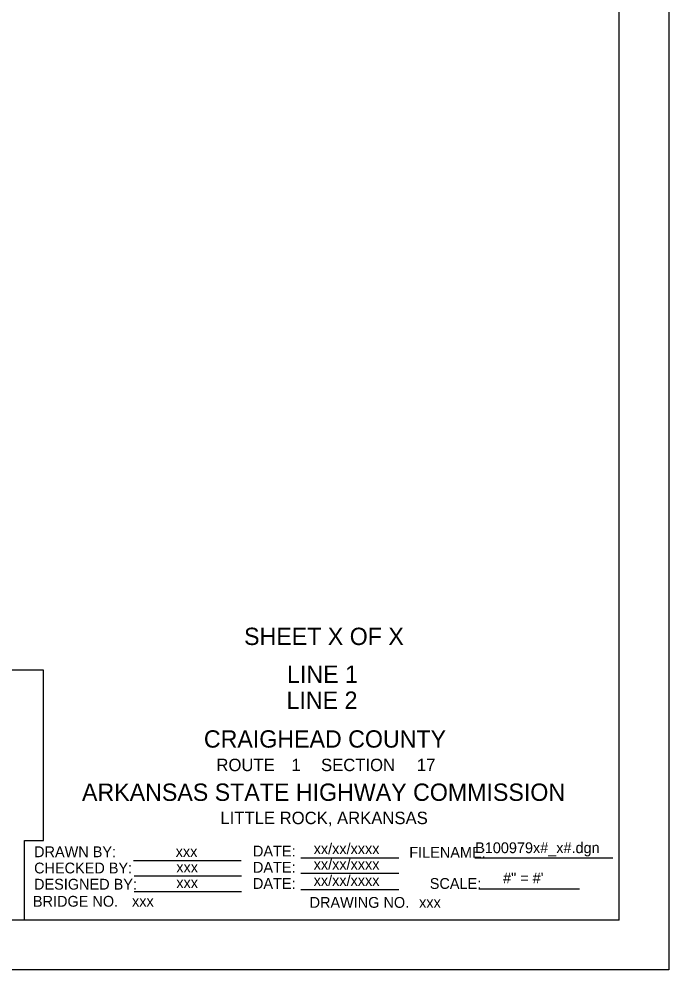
# Model space of a CAD drawing. Extents: x 16 to 1228740, y 11 to 152440.
# Drawn here: x 17.864 to 18.49, y 10.709 to 11.626 of the extents above; entities that cross this region are included whole.
import ezdxf

# ---------------------------------------------------------------- set-up
doc = ezdxf.new("R2010")
doc.units = 0
for name, color, linetype in [('B_Copy In', 7, 'Continuous'), ('B_County and Route', 7, 'Continuous'), ('B_Text', 7, 'Continuous'), ('B_Title Text', 7, 'Continuous'), ('R_Border', 7, 'Continuous'), ('R_No Plot', 7, 'Continuous')]:
    doc.layers.add(name, color=color, linetype=linetype)

msp = doc.modelspace()

# ---------------------------------------------------------------- linework, layer by layer
at = {"layer": 'B_Text'}
for p, q in [((18.13559, 10.81765), (18.23009, 10.81765)), ((18.30318, 10.81765), (18.43623, 10.81765)), ((17.97449, 10.81515), (18.07809, 10.81515)), ((17.97509, 10.80015), (18.07869, 10.80015)), ((18.13559, 10.80265), (18.23009, 10.80265)), ((18.13559, 10.80265), (18.23009, 10.80265)), ((17.97509, 10.78515), (18.07869, 10.78515)), ((18.13559, 10.78703), (18.23009, 10.78703)), ((18.30706, 10.78765), (18.40419, 10.78765))]:
    msp.add_line(p, q, dxfattribs=at)
at = {"layer": 'R_Border'}
for q in [(18.44221, 12.49475), (15.78327, 10.75755)]:
    msp.add_line((18.44221, 10.75755), q, dxfattribs=at)
msp.add_lwpolyline([(15.65694, 12.54282), (18.49027, 12.54282), (18.49027, 10.70949), (15.65694, 10.70949)], close=True, dxfattribs=at)
at = {"layer": 'R_No Plot'}
for p, q in [((17.888, 10.99864), (17.47349, 10.99864)), ((17.888, 10.83424), (17.888, 10.99864)), ((17.86946, 10.83424), (17.888, 10.83424)), ((17.86946, 10.75755), (17.86946, 10.83424))]:
    msp.add_line(p, q, dxfattribs=at)

# ---------------------------------------------------------------- texts
at = {"layer": 'B_Copy In'}
for s, height, p in [('SHEET X OF X', 0.0167, (18.08103, 11.02272)), ('LINE 1', 0.0167, (18.1224, 10.98626)), ('LINE 2', 0.0167, (18.12198, 10.96121)), ('xxx', 0.0104, (18.01519, 10.81846)), ('xx/xx/xxxx', 0.0104, (18.14808, 10.82119)), ('B100979x#_x#.dgn', 0.0104, (18.30362, 10.8221)), ('xx/xx/xxxx', 0.0104, (18.14808, 10.80619)), ('xxx', 0.0104, (18.01579, 10.80346)), ('xx/xx/xxxx', 0.0104, (18.14808, 10.79057)), ('#" = #\'', 0.0104, (18.3305, 10.79302)), ('xxx', 0.0104, (18.01579, 10.78846)), ('xxx', 0.010417, (17.97312, 10.7706)), ('xxx', 0.010417, (18.24962, 10.76944))]:
    msp.add_text(s, height=height, dxfattribs=at).set_placement(p)
at = {"layer": 'B_County and Route'}
for s, height, p in [('CRAIGHEAD COUNTY', 0.0167, (18.04232, 10.92383)), ('1', 0.012, (18.12661, 10.90115)), ('17', 0.012, (18.24748, 10.90115))]:
    msp.add_text(s, height=height, dxfattribs=at).set_placement(p)
at = {"layer": 'B_Text'}
for s, height, p in [('DRAWN BY:', 0.010417, (17.87879, 10.8182)), ('DATE:', 0.010417, (18.08959, 10.8189)), ('FILENAME:', 0.010417, (18.24018, 10.81765)), ('CHECKED BY:', 0.0104166, (17.87879, 10.80257)), ('DATE:', 0.010417, (18.08959, 10.80328)), ('DESIGNED BY:', 0.0104166, (17.87879, 10.78695)), ('DATE:', 0.010417, (18.08959, 10.78765)), ('SCALE:', 0.010417, (18.25989, 10.78765)), ('BRIDGE NO.', 0.010417, (17.87767, 10.77048)), ('DRAWING NO.', 0.0104166, (18.14412, 10.76942))]:
    msp.add_text(s, height=height, dxfattribs=at).set_placement(p)
at = {"layer": 'B_Title Text'}
for s, height, p in [('ROUTE          SECTION ', 0.012, (18.0544, 10.90115)), ('ARKANSAS STATE HIGHWAY COMMISSION', 0.0167, (17.92492, 10.8725)), ('LITTLE ROCK, ARKANSAS', 0.012, (18.05823, 10.85007))]:
    msp.add_text(s, height=height, dxfattribs=at).set_placement(p)

doc.saveas('drawing.dxf')
